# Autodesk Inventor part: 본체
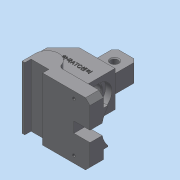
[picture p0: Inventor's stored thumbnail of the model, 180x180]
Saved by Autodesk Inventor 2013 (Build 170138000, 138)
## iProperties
Created: 2016-11
Part Number: 본체
Material: 일반
Document SubType Name: Modeling
Designer: Administrator
Density: 1 g/cm^3
Mass: 170.814 g
Surface Area: 317.29 cm^2
Volume: 170.814 cm^3
Author: Administrator
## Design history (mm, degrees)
sketch "스케치1"
  geometry: L1 (-13, 0)-(-13, -15); L2 (-13, -15)-(-10, -15); L3 (-10, -15)-(-10, -8); L4 (-10, -8)-(10, -8); L5 (10, -8)-(10, -15); L6 (10, -15)-(63, -15); L7 (17.292, 0)-(63, 0); L8 (63, 0)-(63, -15); A1 r 5 centre (17.292, 5) between (12.488, 3.611) and (17.292, 0); A2 r 13 centre (0, 0) between (12.488, 3.611) and (-13, 0); 1 further point
  constraints: 16 end point, 4 point on circle, 3 parallel, 2 centre point, 2 perpendicular, 2 tangent, 2 vertical, 1 coincident, 1 collinear, 1 horizontal alignment
  dimensions: "d2" = 3 distance of L1.end L2.end; "d3" = 7 distance of L2.end L3.end; "d4" = 20 distance of L3.end L4.end; "d5" = 63 horizontal distance of L6.end point (0, 0); "d6" = 15 distance of L7.end L6.end; "d8" = 5 radius of A1; "d9" = 15 distance of L1.start L1.end; "d10" = 7 distance of L4.end L5.end; "d11" = 13 radius of A2
extrude "돌출1" new body sketch "스케치1" stored distance "d12" = 70; taper "d13" = 0 deg
sketch "스케치2"
  geometry: L1 (-27, 27)-(-27, -3); L2 (-27, -3)-(31, -3); L3 (31, -3)-(31, 45); L4 (31, 45)-(-9, 45); L5 (-9, 45)-(-27, 27); L6 (17.292, 0)-(63, 0) reference; L7 (63, 0)-(63, -15) reference; L8 (63, -15)-(10, -15) reference; L9 (10, -15)-(10, -8) reference; L10 (10, -8)-(-10, -8) reference; L11 (-10, -8)-(-10, -15) reference; L12 (-10, -15)-(-13, -15) reference; L13 (-13, -15)-(-13, 0) reference; L14 (17.292, 0)-(63, 0) reference; L15 (63, 0)-(63, -15) reference; L16 (63, -15)-(10, -15) reference; L17 (10, -15)-(10, -8) reference; L18 (10, -8)-(-10, -8) reference; L19 (-10, -8)-(-10, -15) reference; L20 (-10, -15)-(-13, -15) reference; L21 (-13, -15)-(-13, 0) reference; A1 r 13 centre (0, 0) between (12.488, 3.611) and (-13, 0) reference; A2 r 5 centre (17.292, 5) between (12.488, 3.611) and (17.292, 0) reference; A3 r 13 centre (0, 0) between (12.488, 3.611) and (-13, 0) reference; A4 r 5 centre (17.292, 5) between (12.488, 3.611) and (17.292, 0) reference; 1 further point
  constraints: 10 end point, 2 parallel, 1 perpendicular, 1 vertical
  dimensions: "d14" = 45 deg angle of L4 L5; "d15" = 30 distance of L1.end L1.start; "d17" = 58 horizontal distance of L3.end L1.start; "d18" = 90 horizontal distance of L6.end L1.start; "d19" = 48 vertical distance of L1.end L4.end; "d20" = 60 vertical distance of L12.end L4.end
extrude "돌출2" join sketch "스케치2" stored distance "d21" = 40; taper "d22" = 0 deg
sketch "스케치3"
  geometry: L1 (31, 0)-(31, 45) reference; L2 (31, 5)-(63, 5); L3 (63, 5)-(63, 0); L4 (-27, 27)-(-9, 45) reference; L5 (-9, 45)-(31, 45) reference; L6 (31, 45)-(31, 0) reference; L7 (17.292, 0)-(31, 0) reference; L8 (-13, -3)-(-13, 0) reference; L9 (-13, -15)-(-13, -3) reference; L10 (-10, -15)-(-13, -15) reference; L11 (-10, -8)-(-10, -15) reference; L12 (10, -8)-(-10, -8) reference; L13 (10, -15)-(10, -8) reference; L14 (63, -15)-(10, -15) reference; L15 (63, 0)-(63, -15) reference; L16 (31, 0)-(63, 0) reference; L17 (-27, -3)-(-27, 27) reference; L18 (-13, -3)-(-27, -3) reference; A1 r 5 centre (17.292, 5) between (12.488, 3.611) and (17.292, 0) reference; A2 r 13 centre (0, 0) between (12.488, 3.611) and (-13, 0) reference; 1 further point
  constraints: 4 end point, 2 point on line, 1 horizontal, 1 midpoint, 1 perpendicular, 1 vertical alignment
  dimensions: "d23" = 5 distance of L2.end L3.end
extrude "돌출3" join sketch "스케치3" distance "d25" = 40; taper "d26" = 0 deg
sketch "스케치4"
  geometry: L1 (0, 40)-(40, 40) reference; L2 (10, 30)-(35, 30); L3 (35, 30)-(35, 10); L4 (35, 10)-(10, 10); L5 (10, 10)-(10, 30); 2 further points
  constraints: 8 end point, 2 parallel, 1 horizontal, 1 perpendicular
  dimensions: "d27" = 20 distance between parallel lines of L4 L2; "d29" = 25 distance of L2.start L2.end; "d30" = 5 horizontal distance of point (40, 0) L3.end; "d31" = 10 distance between parallel lines of L2 L1
extrude "돌출4" join sketch "스케치4" distance "d32" = 30; taper "d33" = 0 deg
sketch "스케치5"
  geometry: L1 (0, 0)-(0, 30) reference; L2 (9, -60)-(62, -60) reference; C1 r 4 at (12.5, 17); 1 further point
  constraints: 1 centre point
  dimensions: "d34" = 8 diameter of C1; "d36" = 77 distance from line of L2 C1.centre; "d37" = 12.5 distance from line of L1 C1.centre
extrude "돌출5" cut sketch "스케치5" stored distance "d38" = 30; taper "d39" = 0 deg
sketch "스케치6"
  geometry: L1 (0, -40)-(0, 0) reference; L2 (55, -60)-(-15, -60) reference; 2 further points
  dimensions: "d40" = 42 distance from line of L2 point (20, -18); "d41" = 20 distance from line of L1 point (20, -18)
hole "구멍1" sketch "스케치6" at (20, -18) diameter "d42" = 20; stored, may be unused: countersink angle "d46" = 90 deg, drill point angle "d48" = 0 deg; dims "d43" = 6, "d44" = 29, "d45" = 7, "d47" = 200
sketch "스케치7"
  geometry: C1 r 14.5 at (35, 42) reference; C2 r 29 at (35, 42); 1 further point
  constraints: 1 centre point, 1 coincident
  dimensions: "d49" = 29 radius of C2
extrude "돌출6" cut sketch "스케치7" distance "d50" = 18; taper "d51" = 0 deg
sketch "스케치8"
  geometry: L1 (70, 0)-(0, 0) reference; L2 (29, 18.608)-(41, 18.608); L3 (41, 18.608)-(41, 0); L4 (41, 0)-(29, 0); L5 (29, 0)-(29, 18.608); A1 r 29 centre (35, 42) between (16.106, 20) and (53.894, 20) reference; 2 further points
  constraints: 8 end point, 2 parallel, 1 collinear, 1 horizontal, 1 midpoint, 1 perpendicular, 1 vertical alignment
  dimensions: "d52" = 12 distance of L3.end L4.end; "d54" = 18.60817 distance of L2.end L3.end
extrude "돌출7" cut sketch "스케치8" distance "d55" = 18; taper "d56" = 0 deg
chamfer "모따기1" distance "d57" = 4; stored, may be unused: second distance "d58" = 2, angle "d59" = 45 deg
sketch "스케치9"
  geometry: L1 (45.708, 15)-(45.708, 0) reference; L2 (0, 70)-(45.708, 70) reference; 3 further points
  constraints: 1 vertical alignment
  dimensions: "d60" = 55 distance of point (27.708, 7.5) point (27.708, 62.5); "d62" = 18 distance from line of point (27.708, 7.5) L1; "d63" = 7.5 distance from line of L2 point (27.708, 62.5)
hole "구멍2" sketch "스케치9" at (27.708, 62.5), (27.708, 7.5) diameter "d64" = 3.242; stored, may be unused: countersink angle "d68" = 90 deg, drill point angle "d70" = 0 deg; dims "d65" = 190, "d66" = 29, "d67" = 7, "d69" = 200
chamfer "모따기2" distance "d71" = 5; stored, may be unused: second distance "d72" = 2, angle "d73" = 45 deg
fillet "모깎기1" dims "d74" = 3
fillet "모깎기2" dims "d75" = 3
chamfer "모따기3" distance "d76" = 1; stored, may be unused: second distance "d77" = 2, angle "d78" = 45 deg
chamfer "모따기4" distance "d79" = 1; stored, may be unused: second distance "d80" = 2, angle "d81" = 45 deg
sketch "스케치10"
  geometry: L1 (31, 8)-(31, 45) reference; L2 (31, 45)-(-9, 45) reference; 1 further point
  constraints: 1 other
  dimensions: "d82" = 25 distance from line of point (6, 27) L1; "d83" = 18 distance from line of point (6, 27) L2
feature "엠보싱1" sketch "스케치10" dims "d84" = 0.5, "d85" = 0
node "솔리드1"
node "절단 모서리 투영1"
node "절단 모서리 투영2"
node "절단 모서리 투영3"
